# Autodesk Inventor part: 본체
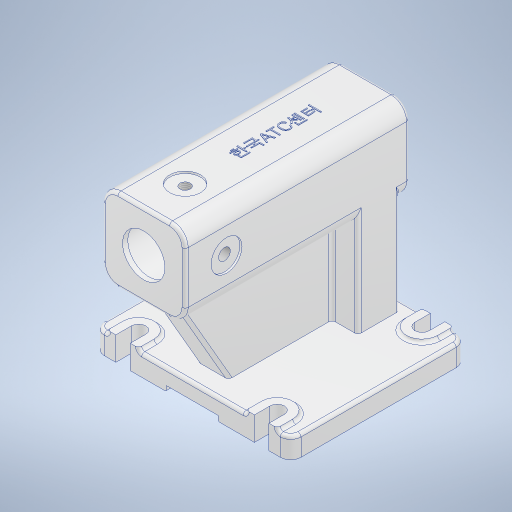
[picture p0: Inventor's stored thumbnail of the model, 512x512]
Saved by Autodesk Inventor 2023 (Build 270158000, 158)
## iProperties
Created: 2024-07
Part Number: 본체
Material: 알루미늄 6061
Document SubType Name: Modeling
Designer: home
Density: 2.7 g/cm^3
Appearance: 알루미늄 - 평지
Mass: 6291.54 g
Surface Area: 2382.6 cm^2
Volume: 2330.2 cm^3
Author: home
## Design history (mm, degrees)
sketch "스케치2"
  geometry: L1 (-40, 40)-(40, 40); L2 (40, 40)-(40, -40); L3 (40, -40)-(-40, -40); L4 (-40, -40)-(-40, 40); L5 (-40, 40)-(40, -40); L6 (40, 40)-(-40, -40); C1 r 20.5 at (0, 0); 1 further point
  constraints: 12 end point, 2 midpoint, 2 parallel, 1 centre point, 1 coincident, 1 horizontal, 1 perpendicular
  dimensions: "d0" = 80 distance of L1.start L1.end; "d1" = 80 distance of L1.end L2.end; "d2" = 41 diameter of C1
extrude "돌출1" new body sketch "스케치2" distance "d3" = 217; taper "d4" = 0 deg
sketch "스케치3"
  geometry: C1 r 20.5 at (0, 0) reference; C2 r 26 at (0, 0)
  constraints: 1 centre point, 1 coincident
  dimensions: "d5" = 52 diameter of C2
extrude "돌출2" cut sketch "스케치3" distance "d6" = 212; taper "d7" = 0 deg
node "작업 평면1"
sketch "스케치4"
  geometry: L1 (80, 0)-(0, 0) reference; L2 (0, 0)-(0, 217) reference; L3 (80, 217)-(0, 217) reference; L4 (80, 0)-(80, 217) reference; L5 (-55, 0)-(135, 0); L6 (135, 0)-(135, 170); L7 (135, 170)-(-55, 170); L8 (-55, 170)-(-55, 0); L9 (40, 0)-(40, 245.035); 2 further points
  constraints: 10 end point, 2 parallel, 1 horizontal, 1 horizontal alignment, 1 perpendicular, 1 vertical
  dimensions: "d9" = 170 distance of L5.end L6.end; "d10" = 190 distance of L5.start L5.end; "d12" = 190 diameter of L8 L9
extrude "돌출3" join sketch "스케치4" distance "d13" = 23; taper "d14" = 0 deg
sketch "스케치5"
  geometry: L1 (-55, -170)-(135, -170) reference; L2 (135, -170)-(135, 0) reference; L3 (-55, 0)-(-55, -170) reference; L4 (80, 0)-(0, 0) reference; L5 (-42, -15)-(-42, 0); L6 (-12, -15)-(-12, 0); L7 (92, -15)-(92, 0); L8 (122, -15)-(122, 0); L9 (-42, -155)-(-42, -170); L10 (-12, -155)-(-12, -170); L11 (92, -155)-(92, -170); L12 (122, -155)-(122, -170); A1 r 15 centre (-27, -15) between (-42, -15) and (-12, -15); A2 r 15 centre (107, -15) between (92, -15) and (122, -15); A3 r 15 centre (107, -155) between (122, -155) and (92, -155); A4 r 15 centre (-27, -155) between (-12, -155) and (-42, -155); 2 further points
  constraints: 16 end point, 8 point on circle, 8 tangent, 4 centre point, 4 perpendicular, 4 point on line, 4 vertical, 3 equal radius, 2 horizontal alignment, 2 vertical alignment, 1 midpoint, 5 other
  dimensions: "d15" = 30 diameter of A1; "d16" = 134 distance of A2.centre A1.centre; "d17" = 67 horizontal distance of point (40, 0) A1.centre (= 0.5 x d16); "d18" = 15 dimension on A2.centre; "d19" = 15 distance from line of L1 A3.centre
extrude "돌출4" cut sketch "스케치5" distance "d20" = 3; taper "d21" = 0 deg
sketch "스케치6"
  geometry: L1 (-42, -170)-(-12, -170) reference; L2 (-42, 0)-(-42, -15) reference; L3 (-12, -15)-(-12, 0) reference; L4 (-12, 0)-(-42, 0) reference; L5 (92, 0)-(92, -15) reference; L6 (122, -15)-(122, 0) reference; L7 (122, 0)-(92, 0) reference; L8 (92, -155)-(92, -170) reference; L9 (92, -170)-(122, -170) reference; L10 (122, -170)-(122, -155) reference; L11 (-34, -15)-(-34, 0); L12 (-20, -15)-(-20, 0); L13 (100, -15)-(100, 0); L14 (114, 0)-(114, -15); L15 (100, -155)-(100, -170); L16 (114, -170)-(114, -155); L17 (-34, -155)-(-34, -170); L18 (-20, -170)-(-20, -155); L19 (-55, -170)-(-55, 0) reference; L20 (135, 0)-(135, -170) reference; A1 r 15 centre (-27, -155) between (-12, -155) and (-42, -155) reference; A2 r 15 centre (-27, -15) between (-42, -15) and (-12, -15) reference; A3 r 15 centre (107, -15) between (92, -15) and (122, -15) reference; A4 r 15 centre (107, -155) between (122, -155) and (92, -155) reference; A5 r 7 centre (-27, -15) between (-34, -15) and (-20, -15); A6 r 7 centre (107, -15) between (100, -15) and (114, -15); A7 r 7 centre (107, -155) between (114, -155) and (100, -155); A8 r 7 centre (-27, -155) between (-20, -155) and (-34, -155); 5 further points
  constraints: 16 end point, 8 point on circle, 5 point on line, 5 vertical alignment, 4 centre point, 1 midpoint, 1 parallel, 1 perpendicular, 4 other
  dimensions: "d22" = 7 radius of A5; "d24" = 7 radius of A6; "d25" = 7 radius of A7; "d26" = 7 radius of A8; "d27" = 21 distance between parallel lines of L19 L17; "d29" = 14 distance between parallel lines of L17 L18; "d30" = 21 distance between parallel lines of L20 L16; "d31" = 14 distance between parallel lines of L16 L15
extrude "돌출5" cut sketch "스케치6" extent not by distance; stored distance "d32" = 3; taper "d33" = 0 deg
sketch "스케치7"
  geometry: L1 (-40, 0)-(40, 0) reference; L2 (40, 0)-(40, 217) reference; L3 (-40, 217)-(40, 217) reference; L4 (-40, 0)-(-40, 217) reference; L5 (-40, 202)-(-130, 150.038); L6 (-130, 170)-(-130, 0) reference; L7 (-177.481, 10)-(-40, 10); L8 (-40, 10)-(-40, 202); L9 (-150, 0)-(-130, 0) reference; 4 further points
  constraints: 6 end point, 2 perpendicular, 1 point on line, 1 vertical alignment
  dimensions: "d34" = 120 deg angle of L6 L5; "d35" = 10 distance between parallel lines of L9 L7; "d36" = 15 distance from line of L3 L5.start
extrude "돌출6" join sketch "스케치7" stored distance "d37" = 30; taper "d38" = 0 deg
sketch "스케치8"
  geometry: L1 (-40, 202)-(-40, 10) reference; L2 (-40, 202)-(-130, 150.038) reference; L3 (-130, 10)-(-130, 150.038) reference; L4 (-130, 10)-(-40, 10) reference; L5 (-40, 10)-(-130, 10); L6 (-130, 10)-(-130, 50); L7 (-130, 50)-(-40, 50); L8 (-40, 50)-(-40, 10); 2 further points
  constraints: 8 end point, 2 parallel, 1 horizontal, 1 perpendicular, 1 point on line
  dimensions: "d39" = 40 distance between parallel lines of L4 L7
extrude "돌출7" join sketch "스케치8" stored distance "d40" = 80; taper "d41" = 0 deg
sketch "스케치9"
  geometry: C1 r 26 at (0, 0) reference; A1 r 32 centre (0, 0) between (0, 32) and (-32, 0); 2 further points
  constraints: 4 point on circle, 1 centre point, 1 coincident
  dimensions: "d42" = 64 diameter of A1
hole "구멍1" sketch "스케치9" at (0, 32), (-32, 0), (0, -32), (32, 0) diameter "d43" = 4.917; stored, may be unused: countersink angle "d47" = 90 deg, drill point angle "d49" = 118 deg; dims "d44" = 12, "d45" = 19.05, "d46" = 4.775, "d48" = 14
sketch "스케치10"
  geometry: L1 (26, 212)-(-26, 212) reference; L2 (26, 0)-(-26, 0) reference; L3 (-40, 0)-(40, 0) reference; L4 (40, 0)-(40, 217) reference; L5 (-40, 217)-(40, 217) reference; L6 (-40, 50)-(-40, 217) reference; L7 (-40, 50)-(-130, 50) reference; L8 (-130, 10)-(-130, 50) reference; L9 (-130, 10)-(-40, 10) reference; L10 (-40, 0)-(-40, 10) reference; L11 (0, 0)-(0, 30.643); L12 (27.155, 0)-(26, 2); L13 (26, 0)-(26, 212) reference; L14 (26, 0)-(27.155, 0); L15 (0, 4.485)-(0, -18.006); 1 further point
  constraints: 8 end point, 3 point on line, 2 vertical, 1 perpendicular
  dimensions: "d51" = 30 deg angle of L13 L12; "d52" = 2 distance from line of L14 L12.end
revolve "회전1" sketch "스케치10" stored, may be unused: angle "d53" = 90 deg
sketch "스케치11"
  geometry: L1 (80, 0)-(0, 0) reference; L2 (40, 0)-(40, -243.457); 1 further point
  constraints: 2 end point, 1 point on line, 1 vertical
  dimensions: "d54" = 177 distance from line of L1 point (40, -177)
hole "구멍2" sketch "스케치11" at (40, -177) diameter "d55" = 10.106; stored, may be unused: countersink angle "d59" = 90 deg, drill point angle "d61" = 118 deg; dims "d56" = 24, "d57" = 30, "d58" = 2, "d60" = 50.25
sketch "스케치12"
  geometry: L1 (0, 0)-(0, 80) reference; L2 (-217, 0)-(-217, 80) reference; L3 (-217, 40)-(-124.786, 40); 2 further points
  constraints: 2 end point, 1 horizontal, 1 midpoint, 1 point on line
  dimensions: "d62" = 177 distance from line of L1 point (-177, 40)
hole "구멍3" sketch "스케치12" at (-177, 40) diameter "d63" = 11.45873; stored, may be unused: countersink angle "d67" = 90 deg, drill point angle "d69" = 118 deg; dims "d64" = 24, "d65" = 30, "d66" = 2, "d68" = 50.25
fillet "모깎기1" dims "d70" = 15
fillet "모깎기3" dims "d72" = 1
fillet "모깎기4" dims "d73" = 2
fillet "모깎기5" dims "d74" = 3
fillet "모깎기6" dims "d75" = 10
fillet "모깎기7" dims "d76" = 3
fillet "모깎기8" dims "d77" = 3
sketch "스케치13"
  geometry: L1 (120, 0)-(0, 0) reference; L2 (35, 0)-(85, 0); L3 (85, 0)-(85, 5); L4 (85, 5)-(35, 5); L5 (35, 5)-(35, 0); 4 further points
  constraints: 8 end point, 2 midpoint, 2 parallel, 1 horizontal, 1 perpendicular, 1 point on line
  dimensions: "d78" = 50 distance of L3.end L4.end; "d79" = 5 distance of L4.end L2.start; "d80" = 25 horizontal distance of point (60, 0) point (35, 2.5) (= 0.5 x d78)
extrude "돌출8" cut sketch "스케치13" extent not by distance; stored distance "d81" = 0; taper "d82" = 0 deg
chamfer "모따기1" distance "d83" = 1; stored, may be unused: second distance "d84" = 2, angle "d85" = 45 deg
fillet "모깎기9" dims "d86" = 3
sketch "스케치14"
  geometry: L1 (74, 3)-(-24, 3) reference; 2 further points
  constraints: 1 vertical alignment, 1 other
  dimensions: "d87" = 90 distance from line of L1 point (25, -87)
feature "엠보싱1" sketch "스케치14" dims "d0" = 80, "d1" = 80, "d88" = 0.5, "d89" = 0
feature "Ӻ耀Ӽ耀Ӿ耀Ԁ耀Ԃ耀Ԅ耀Ԇ耀Ԉ耀" dims "d0" = 80, "d1" = 80, "d2" = 41, "d3" = 217, "d4" = 0, "d5" = 52, "d6" = 212, "d7" = 0, "d8" = 110, "d9" = 170, "d10" = 190, "d12" = 190, "d13" = 23, "d14" = 0, "d15" = 30, "d16" = 134, "d17" = 67 (= 0.5 x d16), "d18" = 15, "d19" = 15, "d20" = 3, "d21" = 0, "d22" = 7, "d24" = 7, "d25" = 7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
node "솔리드1"
mirror "미러1"
node "투영된 루프1"
node "투영된 루프2"
node "투영된 루프3"
node "투영된 루프4"
node "투영된 루프5"
node "투영된 루프6"
node "투영된 루프7"
node "투영된 루프8"
feature "A9D066F2-1C7D-4E18-AEED-F7BC21143FA4" dims "d43" = 4.917, "d44" = 12, "d45" = 19.05, "d46" = 4.775, "d47" = 90 deg, "d48" = 14, "d49" = 118 deg
